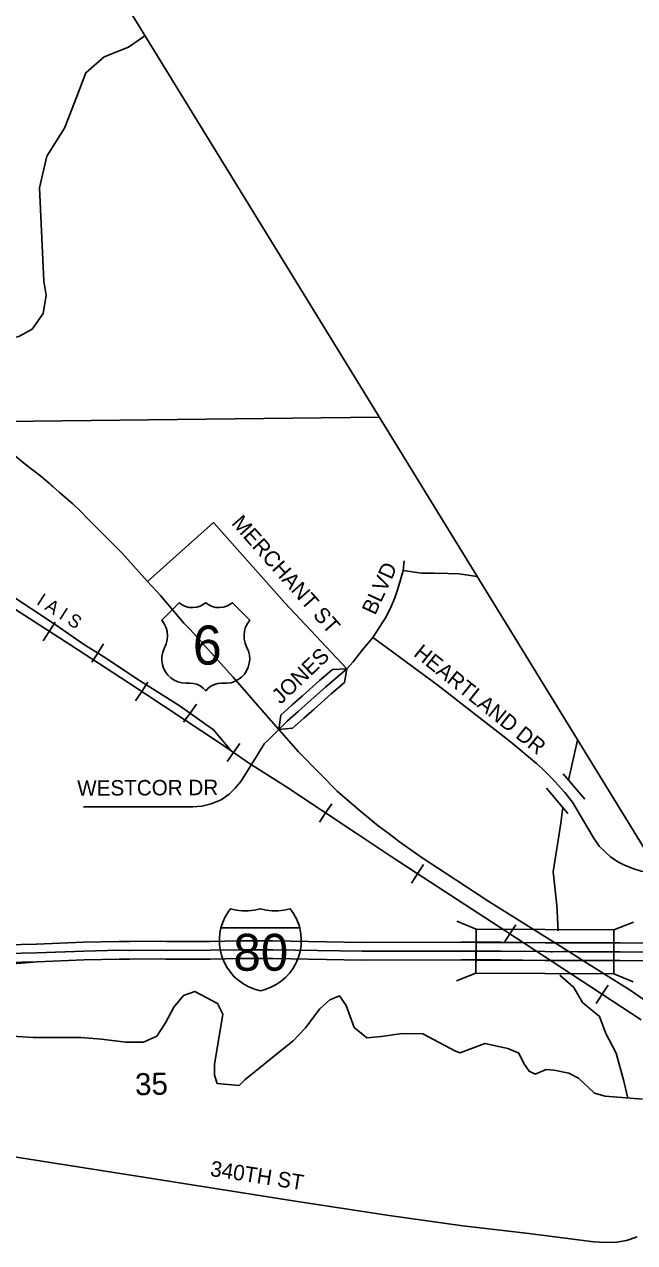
# Model space of a CAD drawing. Extents: x 281.94 to 289.14, y 116.09 to 120.89.
# Drawn here: x 286.097 to 286.65, y 117.691 to 118.797 of the extents above; entities that cross this region are included whole.
import ezdxf

# ---------------------------------------------------------------- set-up
doc = ezdxf.new("R2010")
doc.units = 0
for name, color, linetype in [('tdCiAdjCityStreetCL', 7, 'Continuous'), ('tdCiCityDivCarto', 7, 'Continuous'), ('tdCiCityDivCL', 7, 'Continuous'), ('tdCiHydroRiver', 7, 'Continuous'), ('tdCiInt', 7, 'Continuous'), ('tdCiIntCL', 7, 'Continuous'), ('tdCiIntRamp', 7, 'Continuous'), ('tdCiMapPltShpe', 7, 'Continuous'), ('tdCiPriCL', 7, 'Continuous'), ('tdCiPriDiv', 7, 'Continuous'), ('tdCiRRCL', 7, 'Continuous'), ('tdCiRROwnerTxt', 7, 'Continuous'), ('tdCiSecText', 7, 'Continuous'), ('tdCiSectLine', 7, 'Continuous'), ('tdCiSectNmbr', 7, 'Continuous'), ('tdCiShieldInt', 7, 'Continuous'), ('tdCiShieldPriUsRte', 7, 'Continuous'), ('tdCiStrucCartoClvrt', 7, 'Continuous'), ('tdCiStrucDataInt', 7, 'Continuous')]:
    doc.layers.add(name, color=color, linetype=linetype)

msp = doc.modelspace()

# ---------------------------------------------------------------- linework, layer by layer
at = {"layer": 'tdCiAdjCityStreetCL'}
for points in [[(286.2084, 118.2913), (286.2315, 118.3119), (286.2684, 118.3447), (286.333, 118.2718), (286.3892, 118.2121), (286.395, 118.2183), (286.4001, 118.225), (286.4048, 118.2306), (286.4129, 118.2404)], [(286.4403, 118.3011), (286.4414, 118.3099)], [(286.4129, 118.2404), (286.425, 118.2593), (286.4295, 118.2686), (286.4327, 118.2765), (286.4356, 118.2847), (286.4381, 118.2927), (286.4403, 118.3011)], [(286.4403, 118.3011), (286.457, 118.2988), (286.4686, 118.2987), (286.481, 118.2986), (286.491, 118.2983), (286.5015, 118.2968), (286.5073, 118.2959)], [(286.4129, 118.2404), (286.4205, 118.2351), (286.4722, 118.1967), (286.5036, 118.1723), (286.5374, 118.1461), (286.5613, 118.1261), (286.5667, 118.1212), (286.5753, 118.1128), (286.5869, 118.0997), (286.5941, 118.0909), (286.6039, 118.0741), (286.6126, 118.0591), (286.6182, 118.0509), (286.6242, 118.0452), (286.6284, 118.0413), (286.635, 118.0369), (286.6412, 118.0339), (286.6486, 118.0309), (286.6562, 118.0285), (286.6663, 118.0275), (286.672, 118.0276)], [(286.1505, 118.0866), (286.22, 118.0866), (286.2496, 118.0866), (286.2578, 118.0873), (286.2661, 118.0895), (286.2753, 118.0932), (286.2824, 118.0982), (286.2881, 118.1036), (286.293, 118.1098), (286.3027, 118.1252), (286.3081, 118.1339), (286.3142, 118.1438), (286.3178, 118.1473), (286.3229, 118.1523), (286.3275, 118.1569)], [(285.8778, 117.7992), (285.9313, 117.7932), (286.0073, 117.7821), (286.0075, 117.782), (286.0259, 117.7789), (286.1992, 117.7517)], [(286.1992, 117.7517), (286.3406, 117.7293), (286.4277, 117.716), (286.4945, 117.7066), (286.5544, 117.6994), (286.6109, 117.6923), (286.6132, 117.692), (286.6236, 117.6913), (286.6341, 117.6918), (286.6429, 117.6933), (286.6528, 117.6965)]]:
    msp.add_lwpolyline(points, dxfattribs=at)
at = {"layer": 'tdCiCityDivCarto'}
for points in [[(286.3274, 118.1569), (286.3399, 118.158), (286.3504, 118.1672), (286.3596, 118.1755), (286.3752, 118.1893), (286.3871, 118.1997), (286.3892, 118.2121)], [(286.3275, 118.1569), (286.3293, 118.17), (286.3397, 118.1792), (286.349, 118.1875), (286.3646, 118.2013), (286.3762, 118.2114), (286.3892, 118.2121)]]:
    msp.add_lwpolyline(points, dxfattribs=at)
at = {"layer": 'tdCiCityDivCL'}
msp.add_lwpolyline([(286.3275, 118.1569), (286.3352, 118.1645), (286.345, 118.1732), (286.3543, 118.1815), (286.3699, 118.1953), (286.3892, 118.2121)], dxfattribs=at)
at = {"layer": 'tdCiHydroRiver'}
for points in [[(286.0059, 118.447), (286.0286, 118.488), (286.0507, 118.5029), (286.075, 118.5101), (286.0916, 118.5134), (286.1038, 118.5201), (286.1138, 118.5344), (286.1165, 118.551), (286.1143, 118.5638), (286.1104, 118.6484), (286.1171, 118.6772), (286.1331, 118.7026), (286.1442, 118.7314), (286.1525, 118.7529), (286.1691, 118.7673), (286.1912, 118.7762), (286.2061, 118.7864)], [(286.5905, 118.1109), (286.5986, 118.1472)], [(286.581, 117.9742), (286.5799, 117.9974), (286.5765, 118.0277), (286.5833, 118.0718), (286.5851, 118.0865)], [(286.6443, 117.8223), (286.6405, 117.8377), (286.6337, 117.8632), (286.6243, 117.881), (286.6186, 117.8966), (286.603, 117.9091), (286.5951, 117.9227), (286.5824, 117.9341)], [(286.2691, 117.8528), (286.2767, 117.8986), (286.2719, 117.9082), (286.2513, 117.9193), (286.2412, 117.9156), (286.2322, 117.905), (286.2248, 117.8907), (286.2169, 117.8785), (286.2047, 117.8732), (286.1888, 117.8732), (286.1666, 117.8759), (286.1481, 117.8775), (286.1269, 117.8775), (286.1047, 117.8775), (286.0856, 117.8785)], [(286.2691, 117.8528), (286.2691, 117.8431), (286.2717, 117.8356), (286.2915, 117.8338), (286.2971, 117.8394), (286.333, 117.8684), (286.3405, 117.8744), (286.3518, 117.8863), (286.3649, 117.9033), (286.3738, 117.9117), (286.3825, 117.9152), (286.3887, 117.9063), (286.3959, 117.8866), (286.4075, 117.8771), (286.4206, 117.8783), (286.4394, 117.881), (286.4581, 117.8807), (286.4879, 117.8649), (286.492, 117.8635), (286.5144, 117.8721), (286.5352, 117.8674), (286.5454, 117.8632), (286.5498, 117.8537), (286.5546, 117.8468), (286.56, 117.8441), (286.5701, 117.8483), (286.5775, 117.8477), (286.5907, 117.845), (286.5993, 117.8406), (286.6139, 117.8268), (286.6237, 117.8242), (286.6574, 117.8214)]]:
    msp.add_lwpolyline(points, dxfattribs=at)
at = {"layer": 'tdCiInt'}
for points in [[(286.0798, 117.9615), (286.1078, 117.9622), (286.1504, 117.9638), (286.1826, 117.9646), (286.1922, 117.9645), (286.1924, 117.9645), (286.2204, 117.9648), (286.2256, 117.9645), (286.2651, 117.9646), (286.2923, 117.965), (286.3174, 117.9651), (286.3222, 117.9651), (286.4032, 117.9637), (286.4931, 117.9639), (286.5111, 117.9639), (286.5264, 117.9638), (286.5293, 117.9638), (286.5691, 117.9634), (286.5747, 117.9633), (286.5757, 117.9633), (286.5855, 117.9634), (286.5907, 117.9634), (286.5989, 117.9633), (286.6089, 117.9633), (286.6142, 117.9633), (286.6274, 117.9632), (286.6373, 117.9632), (286.6587, 117.9629)], [(286.0802, 117.9455), (286.1083, 117.9462), (286.1509, 117.9478), (286.1827, 117.9486), (286.192, 117.9485), (286.1924, 117.9485), (286.22, 117.9488), (286.2252, 117.9485), (286.2653, 117.9486), (286.2925, 117.949), (286.3174, 117.9491), (286.322, 117.9491), (286.4031, 117.9477), (286.4931, 117.9479), (286.5111, 117.9479), (286.5262, 117.9478), (286.5291, 117.9478), (286.5689, 117.9474), (286.5746, 117.9473), (286.5758, 117.9473), (286.5856, 117.9474), (286.5907, 117.9474), (286.5988, 117.9473), (286.6088, 117.9473), (286.6141, 117.9473), (286.6274, 117.9472), (286.6373, 117.9472), (286.6586, 117.9469)]]:
    msp.add_lwpolyline(points, dxfattribs=at)
at = {"layer": 'tdCiIntCL'}
msp.add_lwpolyline([(286.08, 117.9535), (286.108, 117.9542), (286.1507, 117.9558), (286.1826, 117.9566), (286.1921, 117.9565), (286.1924, 117.9565), (286.2202, 117.9568), (286.2254, 117.9565), (286.2652, 117.9566), (286.2924, 117.957), (286.3174, 117.9571), (286.3221, 117.9571), (286.4031, 117.9557), (286.4931, 117.9559), (286.5111, 117.9559), (286.5263, 117.9558), (286.5292, 117.9558), (286.569, 117.9554), (286.5747, 117.9553), (286.5757, 117.9553), (286.5855, 117.9554), (286.5907, 117.9554), (286.5988, 117.9553), (286.6089, 117.9553), (286.6142, 117.9553), (286.6274, 117.9552), (286.6373, 117.9552), (286.6587, 117.9549)], dxfattribs=at)
at = {"layer": 'tdCiIntRamp'}
msp.add_lwpolyline([(286.0421, 117.9405), (286.1083, 117.9462)], dxfattribs=at)
at = {"layer": 'tdCiMapPltShpe'}
msp.add_lwpolyline([(286.7119, 117.9469), (286.7118, 117.9629), (285.5135, 119.9142)], dxfattribs=at)
at = {"layer": 'tdCiPriCL'}
msp.add_lwpolyline([(286.0786, 118.4131), (286.099, 118.3966), (286.1117, 118.3868), (286.1199, 118.3797), (286.121, 118.3787), (286.1226, 118.3774), (286.1284, 118.3723), (286.1372, 118.3647), (286.1388, 118.3633), (286.1407, 118.3616), (286.1474, 118.3553), (286.155, 118.3474), (286.1724, 118.3298), (286.1852, 118.3172), (286.2084, 118.2913), (286.2202, 118.2784), (286.2414, 118.2535), (286.2472, 118.2477), (286.283, 118.2076), (286.2862, 118.2043), (286.3143, 118.1719), (286.3275, 118.1569), (286.3455, 118.1366), (286.3659, 118.1159), (286.3806, 118.1011), (286.3999, 118.0844), (286.4176, 118.0696), (286.4276, 118.0622), (286.4369, 118.055), (286.4577, 118.0405), (286.4784, 118.0269), (286.5181, 118.0009), (286.5907, 117.9554), (286.6044, 117.9467), (286.6415, 117.9235), (286.6445, 117.9215), (286.7118, 117.8754)], dxfattribs=at)
at = {"layer": 'tdCiPriDiv'}
msp.add_lwpolyline([(286.0786, 118.4131), (286.099, 118.3966), (286.1117, 118.3868), (286.1199, 118.3797), (286.121, 118.3787), (286.1226, 118.3774), (286.1284, 118.3723), (286.1372, 118.3647), (286.1388, 118.3633), (286.1407, 118.3616), (286.1474, 118.3553), (286.155, 118.3474), (286.1724, 118.3298), (286.1852, 118.3172), (286.2084, 118.2913), (286.2202, 118.2784), (286.2414, 118.2535), (286.2472, 118.2477), (286.283, 118.2076), (286.2862, 118.2043), (286.3143, 118.1719), (286.3275, 118.1569), (286.3455, 118.1366), (286.3659, 118.1159), (286.3806, 118.1011), (286.3999, 118.0844), (286.4176, 118.0696), (286.4276, 118.0622), (286.4369, 118.055), (286.4577, 118.0405), (286.4784, 118.0269), (286.5181, 118.0009), (286.5907, 117.9554), (286.6044, 117.9467), (286.6415, 117.9235), (286.6445, 117.9215), (286.7118, 117.8754)], dxfattribs=at)
at = {"layer": 'tdCiRRCL'}
for points in [[(286.2842, 118.1377), (286.2682, 118.1566), (286.2373, 118.1788), (286.1989, 118.2029), (286.1713, 118.2213), (286.1504, 118.2344), (286.1255, 118.2515), (286.0808, 118.2813), (286.0541, 118.2977), (286.0346, 118.3018)], [(286.2842, 118.1377), (286.2682, 118.1566), (286.2373, 118.1788), (286.1989, 118.2029), (286.1713, 118.2213), (286.1504, 118.2344), (286.1255, 118.2515), (286.0808, 118.2813), (286.0541, 118.2977), (286.0346, 118.3018)], [(286.0836, 118.2691), (286.1379, 118.2339), (286.1909, 118.1995), (286.2738, 118.1449), (286.2842, 118.1377), (286.3009, 118.126), (286.334, 118.1051), (286.3987, 118.0623), (286.4286, 118.0424), (286.4521, 118.0269), (286.5334, 117.9739), (286.594, 117.9344), (286.6562, 117.8935)], [(286.0836, 118.2691), (286.1379, 118.2339), (286.1909, 118.1995), (286.2738, 118.1449), (286.2842, 118.1377), (286.3009, 118.126), (286.334, 118.1051), (286.3987, 118.0623), (286.4286, 118.0424), (286.4521, 118.0269), (286.5334, 117.9739), (286.594, 117.9344), (286.6562, 117.8935)], [(286.1139, 118.2375), (286.1193, 118.2459), (286.1248, 118.2543)], [(286.1686, 118.2348), (286.1633, 118.2263), (286.1579, 118.2179)], [(286.1977, 118.183), (286.2032, 118.1914), (286.2087, 118.1998)], [(286.2529, 118.1799), (286.247, 118.1718), (286.2412, 118.1637)], [(286.2807, 118.1279), (286.2865, 118.1361), (286.2922, 118.1443)], [(286.3645, 118.0729), (286.37, 118.0812), (286.3756, 118.0895)], [(286.448, 118.0176), (286.4534, 118.026), (286.4589, 118.0344)], [(286.5317, 117.963), (286.5372, 117.9714), (286.5427, 117.9798)], [(286.6154, 117.9083), (286.6209, 117.9167), (286.6264, 117.925)]]:
    msp.add_lwpolyline(points, dxfattribs=at)
at = {"layer": 'tdCiSectLine'}
msp.add_lwpolyline([(284.9764, 118.4314), (285.1807, 118.4315), (285.6871, 118.4319), (286.4184, 118.4403)], dxfattribs=at)
at = {"layer": 'tdCiShieldInt'}
msp.add_line((286.2751, 117.9769), (286.3465, 117.9769), dxfattribs=at)
for points in [[(286.297, 117.9923), (286.2997, 117.9923), (286.3051, 117.9929), (286.3108, 117.9942), (286.3161, 117.993), (286.3214, 117.9923), (286.3269, 117.9923), (286.3323, 117.9929), (286.3379, 117.9942), (286.341, 117.9898), (286.3436, 117.985), (286.3456, 117.98), (286.3465, 117.9769), (286.3475, 117.9716), (286.3479, 117.9662), (286.3477, 117.9607), (286.3468, 117.9554), (286.3454, 117.9502), (286.3433, 117.9452), (286.3406, 117.9404), (286.3375, 117.936), (286.3338, 117.9321), (286.3297, 117.9285), (286.3252, 117.9255), (286.3204, 117.923), (286.3153, 117.9211), (286.3108, 117.9199), (286.3056, 117.9213), (286.3005, 117.9233), (286.2957, 117.9259), (286.2913, 117.929), (286.2872, 117.9326), (286.2836, 117.9367), (286.2805, 117.9411), (286.278, 117.9459), (286.276, 117.9509), (286.2746, 117.9562), (286.2738, 117.9615), (286.2737, 117.967), (286.2742, 117.9724), (286.2751, 117.9769), (286.2767, 117.9821), (286.279, 117.987), (286.2818, 117.9917), (286.2837, 117.9942), (286.2889, 117.993), (286.2943, 117.9923)], [(286.2751, 117.9769), (286.2767, 117.9821), (286.279, 117.987), (286.2818, 117.9917), (286.2837, 117.9942), (286.2889, 117.993), (286.2943, 117.9923), (286.2997, 117.9923), (286.3051, 117.9929), (286.3108, 117.9942), (286.3161, 117.993), (286.3214, 117.9923), (286.3269, 117.9923), (286.3323, 117.9929), (286.3379, 117.9942), (286.341, 117.9898), (286.3436, 117.985), (286.3456, 117.98), (286.3465, 117.9769)], [(286.3108, 117.9199), (286.3056, 117.9213), (286.3005, 117.9233), (286.2957, 117.9259), (286.2913, 117.929), (286.2872, 117.9326), (286.2836, 117.9367), (286.2805, 117.9411), (286.278, 117.9459), (286.276, 117.9509), (286.2746, 117.9562), (286.2738, 117.9615), (286.2737, 117.967), (286.2742, 117.9724), (286.2751, 117.9769), (286.3465, 117.9769), (286.3475, 117.9716), (286.3479, 117.9662), (286.3477, 117.9607), (286.3468, 117.9554), (286.3454, 117.9502), (286.3433, 117.9452), (286.3406, 117.9404), (286.3375, 117.936), (286.3338, 117.9321), (286.3297, 117.9285), (286.3252, 117.9255), (286.3204, 117.923), (286.3153, 117.9211)]]:
    msp.add_lwpolyline(points, close=True, dxfattribs=at)
at = {"layer": 'tdCiShieldPriUsRte'}
msp.add_lwpolyline([(286.2933, 118.264), (286.3012, 118.2561), (286.2991, 118.2531), (286.2974, 118.2498), (286.2964, 118.2462), (286.296, 118.2425), (286.2962, 118.2389), (286.297, 118.2352), (286.2983, 118.2318), (286.3, 118.228), (286.3009, 118.2244), (286.3012, 118.2207), (286.3008, 118.217), (286.2999, 118.2135), (286.2983, 118.2101), (286.2963, 118.2071), (286.2937, 118.2044), (286.2907, 118.2022), (286.2874, 118.2005), (286.2839, 118.1994), (286.2802, 118.199), (286.2757, 118.1989), (286.2723, 118.1986), (286.2691, 118.1977), (286.266, 118.1962), (286.2633, 118.1942), (286.2613, 118.192), (286.2589, 118.1945), (286.2561, 118.1964), (286.2531, 118.1979), (286.2498, 118.1987), (286.2468, 118.1989), (286.2434, 118.1989), (286.2397, 118.1992), (286.2361, 118.2002), (286.2327, 118.2017), (286.2297, 118.2037), (286.227, 118.2063), (286.2248, 118.2092), (286.2231, 118.2125), (286.2219, 118.216), (286.2214, 118.2196), (286.2215, 118.2233), (286.2222, 118.227), (286.2235, 118.2304), (286.2254, 118.2348), (286.2263, 118.2384), (286.2266, 118.242), (286.2262, 118.2457), (286.2253, 118.2493), (286.2237, 118.2527), (286.2213, 118.2561), (286.2372, 118.2719), (286.2399, 118.27), (286.243, 118.2685), (286.2463, 118.2677), (286.2497, 118.2675), (286.2531, 118.2679), (286.2563, 118.2689), (286.2593, 118.2705), (286.2613, 118.2719), (286.264, 118.27), (286.2671, 118.2685), (286.2704, 118.2677), (286.2739, 118.2675), (286.2772, 118.2679), (286.2804, 118.2689), (286.2834, 118.2705), (286.2854, 118.2719)], close=True, dxfattribs=at)
at = {"layer": 'tdCiStrucCartoClvrt'}
for p, q in [((286.5856, 118.1166), (286.6051, 118.0938)), ((286.5704, 118.1036), (286.5899, 118.0808))]:
    msp.add_line(p, q, dxfattribs=at)
at = {"layer": 'tdCiStrucDataInt'}
for p, q in [((286.5066, 117.9637), (286.6316, 117.9631)), ((286.5596, 117.9636), (286.6096, 117.9633)), ((286.5065, 117.9477), (286.6315, 117.9471)), ((286.5596, 117.9476), (286.6096, 117.9473))]:
    msp.add_line(p, q, dxfattribs=at)
for points in [[(286.5066, 117.9757), (286.5065, 117.9557), (286.5064, 117.9357), (286.4887, 117.9287)], [(286.6316, 117.9751), (286.5066, 117.9757), (286.489, 117.9829)], [(286.6314, 117.9351), (286.6315, 117.9551), (286.6316, 117.9751), (286.6493, 117.9821)], [(286.5065, 117.9557), (286.569, 117.9554), (286.6315, 117.9551)], [(286.5064, 117.9357), (286.6314, 117.9351), (286.6491, 117.9279)]]:
    msp.add_lwpolyline(points, dxfattribs=at)
msp.add_lwpolyline([(286.5066, 117.9757), (286.6316, 117.9751), (286.6314, 117.9351), (286.5064, 117.9357)], close=True, dxfattribs=at)

# ---------------------------------------------------------------- texts
at = {"layer": 'tdCiRROwnerTxt'}
msp.add_text('I A I S', height=0.012, rotation=327.328, dxfattribs=at).set_placement((286.107, 118.2711))
at = {"layer": 'tdCiSecText'}
for s, rotation, p in [('MERCHANT ST', 311.5677, (286.284, 118.3437)), ('BLVD', 65.4062, (286.415, 118.26)), ('JONES', 43.4062, (286.3292, 118.1792)), ('HEARTLAND DR', 321.2492, (286.449, 118.2244)), ('WESTCOR DR', 0.2632, (286.1447, 118.0968)), ('340TH ST', 351.1024, (286.2647, 117.7519))]:
    msp.add_text(s, height=0.014, rotation=rotation, dxfattribs=at).set_placement(p)
at = {"layer": 'tdCiSectNmbr'}
msp.add_text('35', height=0.02, rotation=1.3963, dxfattribs=at).set_placement((286.1974, 117.8249))
at = {"layer": 'tdCiShieldInt'}
msp.add_text('80', height=0.03348, dxfattribs=at).set_placement((286.2863, 117.938))
at = {"layer": 'tdCiShieldPriUsRte'}
msp.add_text('6', height=0.0354, dxfattribs=at).set_placement((286.2495, 118.2158))

doc.saveas('drawing.dxf')
